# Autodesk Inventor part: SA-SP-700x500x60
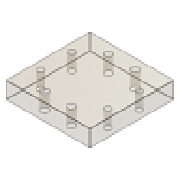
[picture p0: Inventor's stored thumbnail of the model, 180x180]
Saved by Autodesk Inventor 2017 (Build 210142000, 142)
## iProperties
Created: 2016-02
Part Number: SA-SP-700x500x60
Material: S 55 C
Description: Support Plate
Document SubType Name: Modeling
Designer: Sandeep
Standard Revision: 1
Manufacturer: FUTABA
Language: en-US
Size Designation: 700x500x60
Categories: <MemberInstance><Categories><Category DisplayName="Mold" InternalName="349578f2-f4d4-4954-8c09-8e99297a61c0" Mnemonic="MOLD"><Category DisplayName="Mold Plates"
Density: 7.85 g/cm^3
Appearance: Polycarbonate - Smoked
IsCustomPart: 1
Author: Sandeep
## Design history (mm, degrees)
sketch "Sketch1"
  geometry: L1 (-250, 350)-(250, 350); L2 (250, 350)-(250, -350); L3 (250, -350)-(-250, -350); L4 (-250, -350)-(-250, 350); 5 further points
  constraints: 8 end point, 2 midpoint, 2 parallel, 1 horizontal, 1 horizontal alignment, 1 perpendicular, 1 vertical alignment
  dimensions: "d68" = 500 distance between parallel lines of L2 L4 (= W_); "d69" = 700 distance between parallel lines of L3 L1 (= L); "d70" = 317 vertical distance of point (0, 0) point (-128, 317) (= 0.5 x RP_L); "d71" = 128 horizontal distance of point (0, 0) point (-128, 317) (= 0.5 x RP_W); "d72" = 243 vertical distance of point (0, 0) point (-205, 243) (= 0.5 x S1_L); "d73" = 205 horizontal distance of point (0, 0) point (-205, 243) (= 0.5 x S1_W)
extrude "Extrusion1" new body sketch "Sketch1" distance "d20" = 60 (= H_); taper "d30" = 0 deg
body "Solid1"
hole "Hole1" sketch "Sketch1" diameter "d74" = 18 (= S1_d1); stored, may be unused: countersink angle "d78" = 90 deg, drill point angle "d80" = 0 deg; dims "d75" = 6, "d76" = 4, "d77" = 2, "d79" = 60 (= H_)
pattern_linear "Rectangular Pattern1" dims "d102" = 243 (computed from S1_L, Ns), "d105" = 410 (computed from S1_W, Nw)
hole "Hole2" sketch "Sketch1" diameter "d81" = 31 (= RP_d1); stored, may be unused: countersink angle "d85" = 90 deg, drill point angle "d87" = 0 deg; dims "d82" = 6, "d83" = 4, "d84" = 2, "d86" = 60 (= H_)
pattern_linear "Rectangular Pattern2" dims "d108" = 634 (computed from RP_L, Nl), "d111" = 256 (computed from RP_W, Nw)
chamfer "Chamfer1" distance "d112" = 0.5; stored, may be unused: second distance "d113" = 2, angle "d114" = 45 deg
other parameters: "L" = 700 [user parameter; used in 1 equation term], "W_" = 500 [user parameter; used in 1 equation term], "H_" = 60 [user parameter; used in 3 equation terms], "RP_W" = 256 [user parameter; used in 2 equation terms], "S1_d1" = 18 [user parameter; used in 1 equation term], "RP_d1" = 31 [user parameter; used in 1 equation term], "S1_L" = 486 [user parameter; used in 2 equation terms], "RP_L" = 634 [user parameter; used in 2 equation terms]
